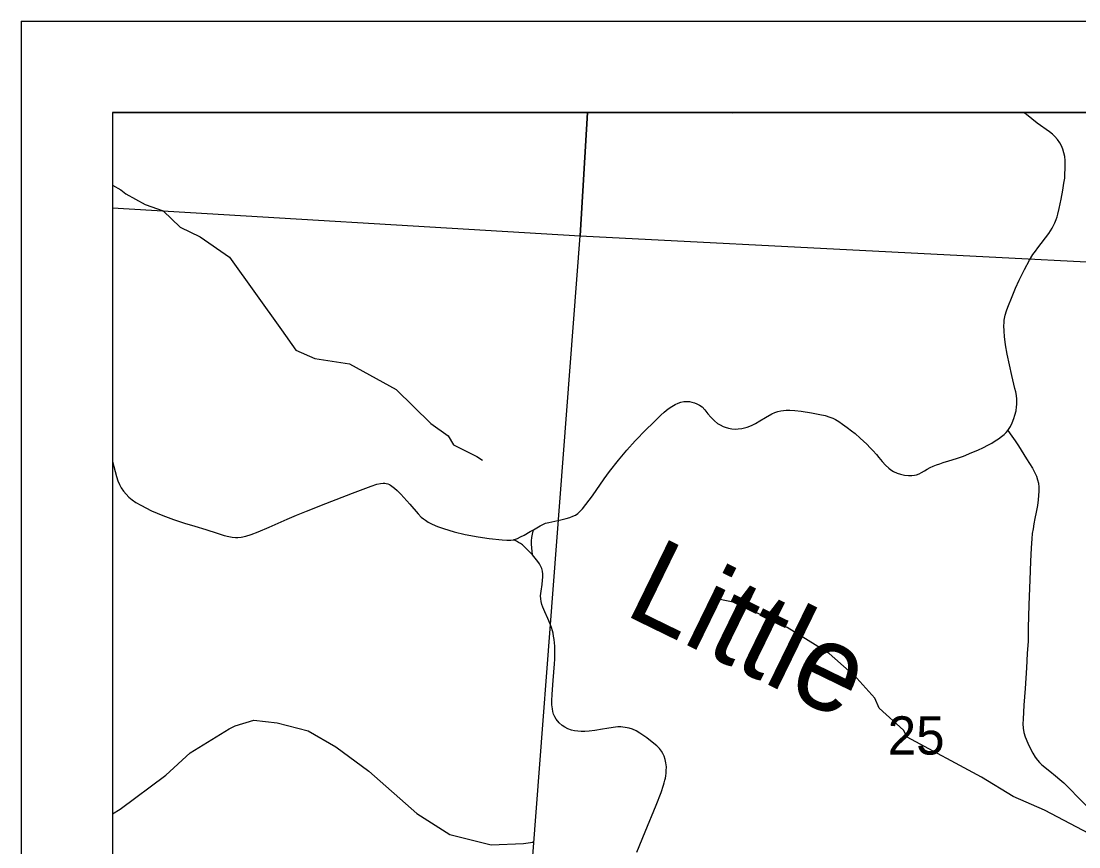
# Model space of a CAD drawing. Extents: x -2.1 to 31.9, y 6.3 to 28.3.
# Drawn here: x -0.066 to 1.092, y 26.44 to 27.344 of the extents above; entities that cross this region are included whole.
import ezdxf

# ---------------------------------------------------------------- set-up
doc = ezdxf.new("R2010")
doc.units = 0
for name, color, linetype in [('Default', 7, 'Continuous'), ('GM_X_Minor_River', 7, 'Continuous'), ('GM_X_Minor_River_Text', 7, 'Continuous'), ('GM_X_Section', 7, 'Continuous'), ('GM_X_Section_Text', 7, 'Continuous'), ('GM_X_Township_Road', 7, 'Continuous'), ('SH_Cut_Line', 7, 'Continuous'), ('SH_Data', 7, 'Continuous')]:
    doc.layers.add(name, color=color, linetype=linetype)

msp = doc.modelspace()

# ---------------------------------------------------------------- linework, layer by layer
at = {"layer": 'Default'}
for points in [[(0.5541, 27.244), (0.0344, 27.244), (0.0344, 27.1394), (0.5464, 27.109)], [(1.5768, 27.244), (0.5541, 27.244), (0.5464, 27.109), (1.5695, 27.0562)]]:
    msp.add_lwpolyline(points, close=True, dxfattribs=at)
msp.add_lwpolyline([(4.7331, 27.244), (0.0344, 27.244), (0.0344, 26.1105), (0.4641, 26.0883), (2.0757, 26.0047), (2.8034, 25.9683), (3.0763, 25.9555), (3.8625, 25.9158)], dxfattribs=at)
at = {"layer": 'GM_X_Minor_River'}
for points in [[(0.7083, 27.244), (0.7127, 27.2435), (0.7149, 27.244)], [(0.0344, 27.1645), (0.0434, 27.1593), (0.049, 27.1549), (0.0701, 27.1432), (0.09, 27.1361), (0.1083, 27.1184), (0.1303, 27.1079), (0.1625, 27.0856), (0.2195, 27.0059), (0.235, 26.9837), (0.2559, 26.9747), (0.2939, 26.9686), (0.3449, 26.9407), (0.3827, 26.9035), (0.4016, 26.8899), (0.4077, 26.8802), (0.433, 26.8673), (0.4395, 26.8631)], [(1.1035, 26.454), (1.0544, 26.4801), (1.0203, 26.4949), (0.9855, 26.5161), (0.9042, 26.56), (0.9, 26.5676), (0.8736, 26.5918), (0.8686, 26.6025), (0.8459, 26.6283), (0.8406, 26.6324), (0.8187, 26.6514), (0.7729, 26.6802), (0.7169, 26.707), (0.6977, 26.7112), (0.6977, 26.7108)], [(0.0344, 26.4759), (0.0428, 26.4811), (0.0927, 26.5185), (0.1195, 26.5429), (0.1622, 26.5692), (0.1686, 26.5723), (0.189, 26.5784), (0.2147, 26.5758), (0.2487, 26.5668), (0.279, 26.5493), (0.3149, 26.5228), (0.3675, 26.4762), (0.4035, 26.4535), (0.4488, 26.4422), (0.4844, 26.4434), (0.4946, 26.4449), (0.4938, 26.4446)]]:
    msp.add_lwpolyline(points, dxfattribs=at)
at = {"layer": 'GM_X_Section'}
msp.add_lwpolyline([(0.5464, 27.109), (1.5695, 27.0562), (1.5197, 26.0415), (0.4693, 26.1002)], close=True, dxfattribs=at)
at = {"layer": 'GM_X_Township_Road'}
for points in [[(0.4731, 26.7762), (0.4753, 26.7768), (0.4777, 26.7776), (0.481, 26.7792), (0.4849, 26.7812), (0.4914, 26.785), (0.495, 26.7871), (0.5023, 26.7914), (0.5054, 26.7928), (0.5084, 26.7941), (0.5118, 26.795), (0.5151, 26.7959), (0.525, 26.7978), (0.5311, 26.7993), (0.535, 26.8005), (0.5382, 26.8018), (0.541, 26.8032), (0.5437, 26.805), (0.546, 26.807), (0.5489, 26.8101), (0.5526, 26.8148), (0.5597, 26.8243), (0.5724, 26.8427), (0.5782, 26.8507), (0.5882, 26.8634), (0.5974, 26.8743), (0.6066, 26.8843), (0.6186, 26.8969), (0.6256, 26.9039), (0.6345, 26.9125), (0.6381, 26.9158), (0.6424, 26.9193), (0.6464, 26.9221), (0.6502, 26.9242), (0.6534, 26.9257), (0.6564, 26.9267), (0.6596, 26.9274), (0.6627, 26.9275), (0.6658, 26.9274), (0.6686, 26.9269), (0.6713, 26.9262), (0.674, 26.9251), (0.6767, 26.9236), (0.6796, 26.9215), (0.6826, 26.9184), (0.6861, 26.9141), (0.6894, 26.9102), (0.6932, 26.9063), (0.6966, 26.9035), (0.6993, 26.9019), (0.7027, 26.9002), (0.705, 26.8993), (0.7087, 26.8983), (0.7124, 26.8977), (0.716, 26.8973), (0.7193, 26.8974), (0.723, 26.8979), (0.7261, 26.8986), (0.729, 26.8995), (0.7336, 26.9013), (0.7381, 26.9035), (0.7429, 26.9062), (0.7492, 26.9101), (0.7559, 26.9139), (0.7593, 26.9154), (0.7627, 26.9166), (0.7657, 26.9174), (0.7687, 26.9178), (0.7718, 26.9181), (0.7758, 26.918), (0.7813, 26.9177), (0.7882, 26.917), (0.7993, 26.9152), (0.8084, 26.9134), (0.8144, 26.9121), (0.8195, 26.9104), (0.8226, 26.9091), (0.8257, 26.9077), (0.8294, 26.9055), (0.8335, 26.9028), (0.8385, 26.8992), (0.8433, 26.8955), (0.8471, 26.8923), (0.8527, 26.8875), (0.8563, 26.8841), (0.8599, 26.8807), (0.8638, 26.8769), (0.8667, 26.8737), (0.8704, 26.8696), (0.873, 26.8662), (0.8766, 26.8618), (0.8803, 26.8577), (0.8842, 26.8544), (0.8864, 26.8528), (0.8893, 26.8509), (0.8933, 26.8491), (0.8969, 26.8479), (0.9012, 26.8469), (0.9056, 26.8464), (0.9093, 26.8464), (0.912, 26.8467), (0.9145, 26.8473), (0.9171, 26.8483), (0.9199, 26.8498), (0.9231, 26.8517), (0.926, 26.8535), (0.9293, 26.8552), (0.9326, 26.8568), (0.9362, 26.8582), (0.9397, 26.8594), (0.9435, 26.8606), (0.9499, 26.8625), (0.9581, 26.8652), (0.9657, 26.8678), (0.975, 26.8715), (0.9814, 26.8743), (0.9877, 26.8772), (0.9925, 26.8797), (0.9967, 26.882), (1.0005, 26.8845), (1.0039, 26.8867), (1.0073, 26.889), (1.0104, 26.8915), (1.0125, 26.8937), (1.0143, 26.8959), (1.0156, 26.8978), (1.0171, 26.9003), (1.0192, 26.9042), (1.021, 26.9088), (1.0221, 26.9124), (1.0233, 26.9173), (1.0239, 26.9216), (1.0241, 26.9241), (1.0241, 26.9266), (1.0241, 26.9302), (1.0236, 26.9341), (1.023, 26.938), (1.0221, 26.9419), (1.0187, 26.9561), (1.0136, 26.9793), (1.0118, 26.9894), (1.0106, 26.9987), (1.0102, 27.0046), (1.01, 27.0106), (1.0101, 27.0136), (1.0104, 27.0167), (1.0115, 27.0222), (1.0128, 27.0267), (1.0142, 27.0309), (1.0189, 27.0424), (1.0227, 27.0515), (1.0266, 27.0602), (1.0324, 27.0721), (1.038, 27.0822), (1.0418, 27.0885), (1.0444, 27.0922), (1.0471, 27.0958), (1.0591, 27.1115), (1.061, 27.1142), (1.0628, 27.1172), (1.0643, 27.1202), (1.0658, 27.1233), (1.0671, 27.1267), (1.0681, 27.1296), (1.0691, 27.1326), (1.0706, 27.1387), (1.0728, 27.149), (1.0744, 27.159), (1.0757, 27.1667), (1.0765, 27.1722), (1.0768, 27.1772), (1.0771, 27.182), (1.0771, 27.1871), (1.077, 27.1912), (1.0765, 27.1957), (1.0757, 27.1998), (1.0744, 27.2038), (1.0729, 27.2074), (1.0711, 27.2107), (1.0686, 27.2143), (1.0657, 27.2176), (1.0631, 27.2203), (1.06, 27.2228), (1.0465, 27.2323), (1.0346, 27.2417), (1.0316, 27.244)], [(1.0143, 26.8959), (1.0186, 26.8895), (1.0222, 26.8843), (1.0258, 26.8791), (1.0348, 26.8648), (1.0413, 26.8544), (1.0436, 26.8501), (1.0456, 26.8457), (1.0469, 26.8417), (1.0478, 26.8379), (1.0482, 26.8338), (1.0483, 26.8293), (1.048, 26.8245), (1.0475, 26.8197), (1.0466, 26.8137), (1.0453, 26.8065), (1.0439, 26.7993), (1.0427, 26.7935), (1.0419, 26.7881), (1.0411, 26.783), (1.0405, 26.7771), (1.0397, 26.7672), (1.039, 26.7524), (1.0383, 26.7324), (1.0374, 26.7047), (1.0368, 26.6919), (1.0366, 26.6799), (1.0364, 26.6651), (1.0356, 26.6514), (1.0346, 26.6358), (1.0332, 26.6134), (1.0319, 26.5949), (1.031, 26.5796), (1.0308, 26.5747), (1.0311, 26.5699), (1.0319, 26.5651), (1.0334, 26.5605), (1.0363, 26.5533), (1.0391, 26.5471), (1.0417, 26.5424), (1.0443, 26.5382), (1.0467, 26.5348), (1.049, 26.5322), (1.0516, 26.5295), (1.0602, 26.5226), (1.0665, 26.5176), (1.0712, 26.5136), (1.0754, 26.5099), (1.0816, 26.5039), (1.0916, 26.4937), (1.106, 26.4794)], [(0.0344, 26.8617), (0.0389, 26.8454), (0.0404, 26.8406), (0.042, 26.8366), (0.044, 26.8329), (0.0465, 26.8292), (0.0492, 26.826), (0.0523, 26.8228), (0.0559, 26.8198), (0.0601, 26.817), (0.0654, 26.8139), (0.0771, 26.8079), (0.0895, 26.8026), (0.101, 26.7983), (0.1132, 26.7942), (0.1244, 26.7909), (0.1364, 26.7872), (0.1488, 26.7833), (0.1565, 26.7809), (0.1617, 26.7795), (0.1653, 26.7789), (0.1691, 26.7786), (0.1716, 26.7786), (0.1753, 26.779), (0.1802, 26.7801), (0.1862, 26.7819), (0.1938, 26.7847), (0.2058, 26.7898), (0.2254, 26.7986), (0.2359, 26.8031), (0.2466, 26.8075), (0.2678, 26.8158), (0.2972, 26.8271), (0.3117, 26.8327), (0.3176, 26.8347), (0.3238, 26.8368), (0.3277, 26.8376), (0.3307, 26.838), (0.3325, 26.838), (0.3341, 26.8377), (0.3357, 26.8373), (0.3374, 26.8367), (0.3388, 26.8359), (0.3403, 26.8349), (0.3429, 26.8327), (0.3461, 26.8299), (0.35, 26.826), (0.3597, 26.8151), (0.3688, 26.8045), (0.3724, 26.801), (0.3746, 26.7991), (0.3768, 26.7974), (0.38, 26.7954), (0.3844, 26.793), (0.3901, 26.7906), (0.3965, 26.7883), (0.4084, 26.7848), (0.4205, 26.782), (0.4345, 26.7794), (0.4468, 26.7775), (0.461, 26.776), (0.4659, 26.7757), (0.4702, 26.7758), (0.4731, 26.7762)], [(0.4941, 26.7596), (0.4932, 26.7673), (0.4929, 26.7713), (0.4928, 26.7749), (0.4932, 26.7785), (0.4939, 26.7821), (0.495, 26.7871)], [(0.6084, 26.4341), (0.6173, 26.4562), (0.6293, 26.4856), (0.6348, 26.4995), (0.6375, 26.5073), (0.6383, 26.5101), (0.639, 26.5127), (0.6395, 26.5151), (0.6399, 26.5176), (0.6403, 26.5205), (0.6405, 26.5232), (0.6406, 26.5276), (0.6401, 26.532), (0.6393, 26.5356), (0.6381, 26.5392), (0.6368, 26.5421), (0.6352, 26.5447), (0.6329, 26.5477), (0.6302, 26.5504), (0.6268, 26.5532), (0.6192, 26.5591), (0.6114, 26.5645), (0.6075, 26.5669), (0.6035, 26.5686), (0.5999, 26.5698), (0.5956, 26.5706), (0.5929, 26.571), (0.5906, 26.5711), (0.5874, 26.5711), (0.5824, 26.5707), (0.5756, 26.5696), (0.5708, 26.5686), (0.5622, 26.5671), (0.5562, 26.5664), (0.5513, 26.5661), (0.5474, 26.566), (0.5438, 26.5664), (0.54, 26.5669), (0.5366, 26.5678), (0.5329, 26.5691), (0.5293, 26.5708), (0.5264, 26.5729), (0.5232, 26.5757), (0.52, 26.5797), (0.5184, 26.5823), (0.5172, 26.5852), (0.5163, 26.5882), (0.5158, 26.591), (0.5154, 26.5955), (0.5153, 26.5997), (0.5157, 26.6071), (0.5168, 26.622), (0.5181, 26.6402), (0.5184, 26.6455), (0.5186, 26.6505), (0.5186, 26.6552), (0.5185, 26.6595), (0.5182, 26.6633), (0.5178, 26.667), (0.5172, 26.6707), (0.5167, 26.6737), (0.516, 26.6765), (0.5149, 26.6799), (0.5139, 26.6828), (0.5109, 26.6898), (0.5074, 26.6973), (0.5052, 26.7022), (0.5043, 26.7053), (0.5034, 26.7086), (0.5031, 26.7114), (0.503, 26.7146), (0.5033, 26.7174), (0.5036, 26.72), (0.5046, 26.7272), (0.505, 26.7317), (0.5052, 26.7353), (0.5053, 26.7384), (0.505, 26.7416), (0.5042, 26.7447), (0.5029, 26.7475), (0.5016, 26.7499), (0.4999, 26.7524), (0.4941, 26.7596), (0.4856, 26.7681), (0.4831, 26.7704), (0.4811, 26.7719), (0.4789, 26.7732), (0.4765, 26.7744), (0.4731, 26.7762)]]:
    msp.add_lwpolyline(points, dxfattribs=at)
at = {"layer": 'SH_Cut_Line'}
msp.add_lwpolyline([(6.8344, 20.444), (6.8344, 27.244), (0.0344, 27.244), (0.0344, 20.444)], dxfattribs=at)
at = {"layer": 'SH_Data'}
for p, q in [((-0.0656, 27.344), (6.9344, 27.344)), ((-0.0656, 27.344), (-0.0656, 20.344)), ((0.0344, 27.244), (0.0344, 20.444)), ((0.0344, 27.244), (6.8344, 27.244))]:
    msp.add_line(p, q, dxfattribs=at)

# ---------------------------------------------------------------- texts
at = {"layer": 'GM_X_Minor_River_Text'}
msp.add_text('Little', height=0.0947, rotation=333.998, dxfattribs=at).set_placement((0.5925, 26.6951))
at = {"layer": 'GM_X_Section_Text'}
msp.add_text('25', height=0.04186, rotation=0, dxfattribs=at).set_placement((0.8828, 26.5409))

doc.saveas('drawing.dxf')
